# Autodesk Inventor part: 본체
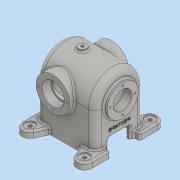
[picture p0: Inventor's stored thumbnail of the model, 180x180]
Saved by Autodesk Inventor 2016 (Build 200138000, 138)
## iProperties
Created: 2024-09
Part Number: 본체
Material: 일반
Document SubType Name: Modeling
Designer: pc-7
Density: 1 g/cm^3
Appearance: 기본값
Author: pc-7
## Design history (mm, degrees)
sketch "스케치1"
  geometry: L1 (-45, 76)-(45, 76); L2 (45, 76)-(45, 0); L3 (45, 0)-(-45, 0); L4 (-45, 0)-(-45, 76); A1 r 45 centre (0, 76) between (45, 76) and (-45, 76); 2 further points
  constraints: 8 end point, 2 midpoint, 2 parallel, 2 point on circle, 1 centre point, 1 coincident, 1 horizontal, 1 perpendicular
  dimensions: "d0" = 90 distance between parallel lines of L2 L4; "d1" = 76 distance between parallel lines of L3 L1
extrude "돌출1" new body sketch "스케치1" stored distance "d2" = 108; taper "d3" = 0 deg
sketch "스케치2"
  geometry: L1 (-45, 0)-(45, 0) reference; C1 r 28.5 at (0, 76); 2 further points
  constraints: 1 centre point, 1 midpoint, 1 vertical alignment
  dimensions: "d4" = 57 diameter of C1; "d5" = 76 distance of point (0, 0) C1.centre
extrude "돌출2" join sketch "스케치2" distance "d6" = 6; taper "d7" = 0 deg
sketch "스케치3"
  geometry: L1 (104.5, 60)-(47.5, 60) reference; C1 r 31 at (76, -14); 1 further point
  constraints: 1 centre point
  dimensions: "d8" = 76 horizontal distance of point (0, 0) C1.centre; "d9" = 62 diameter of C1; "d10" = 74 distance from line of L1 C1.centre
extrude "돌출3" join sketch "스케치3" stored distance "d11" = 108; taper "d12" = 0 deg
sketch "스케치4"
  geometry: L1 (104.5, 60)-(47.5, 60) reference; L2 (76, 60)-(76, -45); L3 (76, -45)-(112, -45); L4 (112, -45)-(112, 45); L5 (112, 45)-(92.5, 45); L6 (92.5, 45)-(92.5, 60); L7 (92.5, 60)-(76, 60); L8 (76, -54)-(121, -54) reference; L9 (121, 54)-(76, 54) reference; 2 further points
  constraints: 12 end point, 4 perpendicular, 1 collinear, 1 midpoint, 1 point on line, 1 vertical
  dimensions: "d18" = 9 distance between parallel lines of L8 L3; "d19" = 9 distance between parallel lines of L9 L5; "d20" = 33 diameter of L6 L2; "d21" = 72 diameter of L4 L2
revolve "회전1" sketch "스케치4" stored, may be unused: angle "d22" = 90 deg
sketch "스케치5"
  geometry: 1 further point
sketch "스케치6"
  geometry: L1 (74, -28.5)-(74, 28.5) reference; 2 further points
  dimensions: "d23" = 76 vertical distance of point (14, -76) point (0, 0); "d24" = 74 distance from line of L1 point (0, 0)
hole "구멍1" sketch "스케치6" at (0, 0) diameter "d25" = 35; stored, may be unused: countersink angle "d29" = 82 deg, drill point angle "d31" = 0 deg; dims "d26" = 6, "d27" = 40, "d28" = 16, "d30" = 25
sketch "스케치7"
  geometry: L1 (-20, 23)-(20, 23); L2 (20, 23)-(20, 0); L3 (20, 0)-(-20, 0); L4 (-20, 0)-(-20, 23); L5 (-45, 0)-(45, 0) reference; 2 further points
  constraints: 8 end point, 2 midpoint, 2 parallel, 1 horizontal, 1 perpendicular
  dimensions: "d32" = 23 distance between parallel lines of L3 L1; "d33" = 40 distance between parallel lines of L2 L4
extrude "돌출4" cut sketch "스케치7" distance "d34" = 108; taper "d35" = 0 deg
sketch "스케치8"
  geometry: L1 (-36, 0)-(-36, 49); L2 (45, 0)-(20, 0) reference; L3 (-45, 0)-(-45, 76) reference; L4 (45, 76)-(45, 0) reference; L5 (-20, 0)-(-45, 0) reference; L6 (20, 23)-(-20, 23) reference; L7 (-20, 23)-(-20, 0) reference; L8 (20, 0)-(20, 23) reference; L9 (36, 0)-(36, 49); L10 (36, 0)-(20, 0); L11 (20, 0)-(20, 23); L12 (20, 23)-(-20, 23); L13 (-20, 23)-(-20, 0); L14 (-36, 0)-(-20, 0); C1 r 36 at (0, 76) reference; A1 r 45 centre (0, 76) between (-36, 49) and (36, 49); 1 further point
  constraints: 15 end point, 5 collinear, 2 point on circle, 2 vertical, 1 centre point, 1 coincident, 1 point on line
  dimensions: "d37" = 9 distance between parallel lines of L3 L1; "d39" = 9 distance between parallel lines of L4 L9; "d40" = 45 radius of A1
extrude "돌출5" cut sketch "스케치8" stored distance "d41" = 91; taper "d42" = 0 deg
node "작업 평면1"
sketch "스케치9"
  geometry: L1 (28.5, 60)-(-28.5, 60) reference; C1 r 7.5 at (0, -14); 1 further point
  constraints: 1 centre point, 1 vertical alignment
  dimensions: "d44" = 74 distance from line of L1 C1.centre; "d45" = 15 diameter of C1
extrude "돌출6" join sketch "스케치9" stored distance "d46" = 91; taper "d47" = 0 deg
node "작업 평면3"
  node "작업 평면2"
sketch "스케치10"
  geometry: L1 (7.5, -28.5)-(7.5, 28.5) reference; C1 r 7.5 at (-66.5, 0); 1 further point
  constraints: 1 centre point, 1 horizontal alignment, 1 midpoint
  dimensions: "d52" = 74 distance from line of L1 C1.centre; "d53" = 15 diameter of C1
extrude "돌출7" join sketch "스케치10" stored distance "d54" = 91; taper "d55" = 0 deg
sketch "스케치11"
  geometry: C1 r 7.5 at (0, 0) reference; 2 further points
  constraints: 1 coincident
hole "구멍2" sketch "스케치11" at (0, 0) diameter "d56" = 4.917; stored, may be unused: countersink angle "d60" = 82 deg, drill point angle "d62" = 0 deg; dims "d57" = 12, "d58" = 40, "d59" = 16, "d61" = 17.1
sketch "스케치12"
  geometry: C1 r 7.5 at (0, 0) reference; C2 r 2.458 at (0, 0) reference; 2 further points
  constraints: 1 coincident
hole "구멍3" sketch "스케치12" at (0, 0) diameter "d63" = 4.917; stored, may be unused: countersink angle "d67" = 82 deg, drill point angle "d69" = 0 deg; dims "d64" = 12, "d65" = 40, "d66" = 16, "d68" = 17.1
sketch "스케치13" dims "d70" = 52
  geometry: C1 r 31 at (0, 0) reference; 3 further points
  constraints: 2 vertical alignment, 1 coincident, 2 other
hole "구멍4" sketch "스케치13" at (0, 26) diameter "d71" = 3.242; stored, may be unused: countersink angle "d75" = 82 deg, drill point angle "d77" = 118 deg; dims "d72" = 8, "d73" = 40, "d74" = 16, "d76" = 10
sketch "스케치14" dims "d81" = 46
  geometry: C1 r 28.5 at (0, 0) reference; C2 r 28.5 at (0, 0) reference; 3 further points
  constraints: 2 vertical alignment, 1 coincident, 2 other
hole "구멍5" sketch "스케치14" at (0, 23) diameter "d82" = 3.242; stored, may be unused: countersink angle "d86" = 82 deg, drill point angle "d88" = 118 deg; dims "d83" = 8, "d84" = 40, "d85" = 16, "d87" = 10
sketch "스케치15"
  geometry: L1 (18, 0)-(18, -10); L2 (18, -10)-(-15, -10); L3 (-15, -10)-(-15, 0); L4 (0, 0)-(0, 108) reference; L5 (0, 26)-(-20.693, 16.79); L6 (25, 0)-(0, 0) reference; L7 (18, 0)-(0, 0); L8 (0, 26)-(0, 0); A1 r 14 centre (-15, 4) between (-20.693, 16.79) and (-15, -10); 1 further point
  constraints: 12 end point, 3 perpendicular, 3 point on line, 2 point on circle, 1 centre point, 1 collinear, 1 tangent, 1 vertical
  dimensions: "d92" = 18 distance between parallel lines of L1 L4; "d94" = 60 distance from line of point (45, 54) L3; "d95" = 36 distance from line of L5.start L2; "d96" = 10 distance between parallel lines of L6 L2; "d97" = 14 distance from line of A1.centre L2
extrude "돌출8" join sketch "스케치15" distance "d98" = 12; taper "d99" = 0 deg
sketch "스케치16"
  geometry: 2 further points
  dimensions: "d100" = 50 vertical distance of point (45, -54) point (-15, -4); "d101" = 60 horizontal distance of point (-15, -4) point (45, -54)
hole "구멍6" sketch "스케치16" at (-15, -4) diameter "d102" = 6.6; stored, may be unused: countersink angle "d106" = 82 deg, drill point angle "d108" = 0 deg; dims "d103" = 8, "d104" = 18, "d105" = 2, "d107" = 10
fillet "모깎기1" dims "d115" = 12
fillet "모깎기2" dims "d116" = 3
fillet "모깎기3" dims "d117" = 3
fillet "모깎기4" dims "d118" = 3
fillet "모깎기5" dims "d119" = 3
fillet "모깎기6" dims "d120" = 3
fillet "모깎기7" dims "d121" = 3
fillet "모깎기8" dims "d122" = 3
fillet "모깎기9" dims "d123" = 3
fillet "모깎기10" dims "d124" = 3
fillet "모깎기11" dims "d125" = 3
fillet "모깎기12" dims "d126" = 3
fillet "모깎기13" dims "d127" = 3
fillet "모깎기14" dims "d128" = 3
fillet "모깎기15" dims "d129" = 3
fillet "모깎기16" dims "d130" = 3
fillet "모깎기17" dims "d131" = 3
fillet "모깎기18" dims "d132" = 3
sketch "스케치17"
  geometry: L1 (-20.739, 38.002)-(20.739, 38.002); L2 (20.739, 38.002)-(20.739, 31.998); L3 (20.739, 31.998)-(-20.739, 31.998); L4 (-20.739, 31.998)-(-20.739, 38.002); L5 (-20.739, 35)-(20.739, 35); L6 (0, 38.002)-(0, 31.998); 2 further points
  constraints: 5 midpoint, 4 end point, 1 vertical alignment, 2 other
  dimensions: "d133" = 35 distance from line of point (0, 0) L5
feature "엠보싱1" sketch "스케치17" dims "d134" = 0.5, "d135" = 0
chamfer "모따기1" distance "d136" = 1; stored, may be unused: second distance "d137" = 2, angle "d138" = 45 deg
chamfer "모따기2" distance "d139" = 1; stored, may be unused: second distance "d140" = 2, angle "d141" = 45 deg
chamfer "모따기3" distance "d142" = 1; stored, may be unused: second distance "d143" = 2, angle "d144" = 45 deg
node "솔리드1"
mirror "대칭1"
pattern_circular "원형 패턴1" dims angle "d79" = 360 deg
mirror "대칭2"
pattern_circular "원형 패턴2" dims angle "d90" = 360 deg
mirror "대칭3"
mirror "대칭4"
pattern_linear "직사각형 패턴1" dims "d111" = 100
node "작업축1"
other parameters: "d43" = 125, "d48" = 0, "d49" = -49
